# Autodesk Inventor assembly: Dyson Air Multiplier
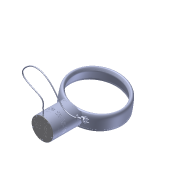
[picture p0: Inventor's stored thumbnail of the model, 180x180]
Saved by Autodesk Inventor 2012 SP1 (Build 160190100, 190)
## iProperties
Created: 2012-11
Part Number: Dyson Air Multiplier
Document SubType Name: Assembly
Designer: Administrateur
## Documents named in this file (8)
- D:\Cours\1-Cours-2013-14\Dropbox\1SI\1. Besoin\Dyson\Composants importés\Dyson Air Multiplier-Assemblage final\Dyson Air Multiplier.iam
- D:\Cours\1-Cours-2013-14\Dropbox\1SI\1. Besoin\Dyson\Composants importés\Dyson Air Multiplier-Assemblage final\Dyson-partie inf. support bras rotation.iam
- D:\Cours\1-Cours-2013-14\Dropbox\1SI\1. Besoin\Dyson\Composants importés\Dyson Air Multiplier-Assemblage final\Dyson-partie inf. support moteur rotation.iam
- D:\Cours\1-Cours-2013-14\Dropbox\1SI\1. Besoin\Dyson\Composants importés\Dyson Air Multiplier-Assemblage final\Dia. 3 x 8.ipt
- D:\Cours\1-Cours-2013-14\Dropbox\1SI\1. Besoin\Dyson\Composants importés\Dyson Air Multiplier-Assemblage final\Vis torks M3x12.ipt
- D:\Cours\1-Cours-2013-14\Dropbox\1SI\1. Besoin\Dyson\Composants importés\Dyson Air Multiplier-Assemblage final\Dyson-partie centre commande.iam
- D:\Cours\1-Cours-2013-14\Dropbox\1SI\1. Besoin\Dyson\Composants importés\Dyson Air Multiplier-Assemblage final\Dyson-partie supérieure complète.iam
- D:\Cours\1-Cours-2013-14\Dropbox\1SI\1. Besoin\Dyson\Composants importés\Dyson Air Multiplier-Assemblage final\Dyson-tube central.iam
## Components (7 placed, 7 different names)
1. Dyson-partie inf. support bras rotation:1 [sub-assembly] — Logement:2
2. Dyson-partie inf. support moteur rotation:1 [sub-assembly]
3. Dia. 3 x 8:1
4. Vis torks M3x12:1
5. Dyson-partie centre commande:1 [sub-assembly] — Logement:2, Placage:1, Placage:2
6. Dyson-partie supérieure complète:1 [sub-assembly] — Logement:1, Angle:1
7. Dyson-tube central:1 [sub-assembly] — Logement:1, Placage:1, Placage:2, Angle:1
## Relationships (5: Insert 2, Mate 2, Angle 1)
- Logement:1 [Insert]: Dyson-partie supérieure complète:1 ↔ Dyson-tube central:1
- Logement:2 [Insert]: Dyson-partie inf. support bras rotation:1 ↔ Dyson-partie centre commande:1
- Placage:1 [Mate]: Dyson-partie centre commande:1 ↔ Dyson-tube central:1
- Placage:2 [Mate]: Dyson-partie centre commande:1 ↔ Dyson-tube central:1
- Angle:1: Dyson-partie supérieure complète:1 ↔ Dyson-tube central:1
